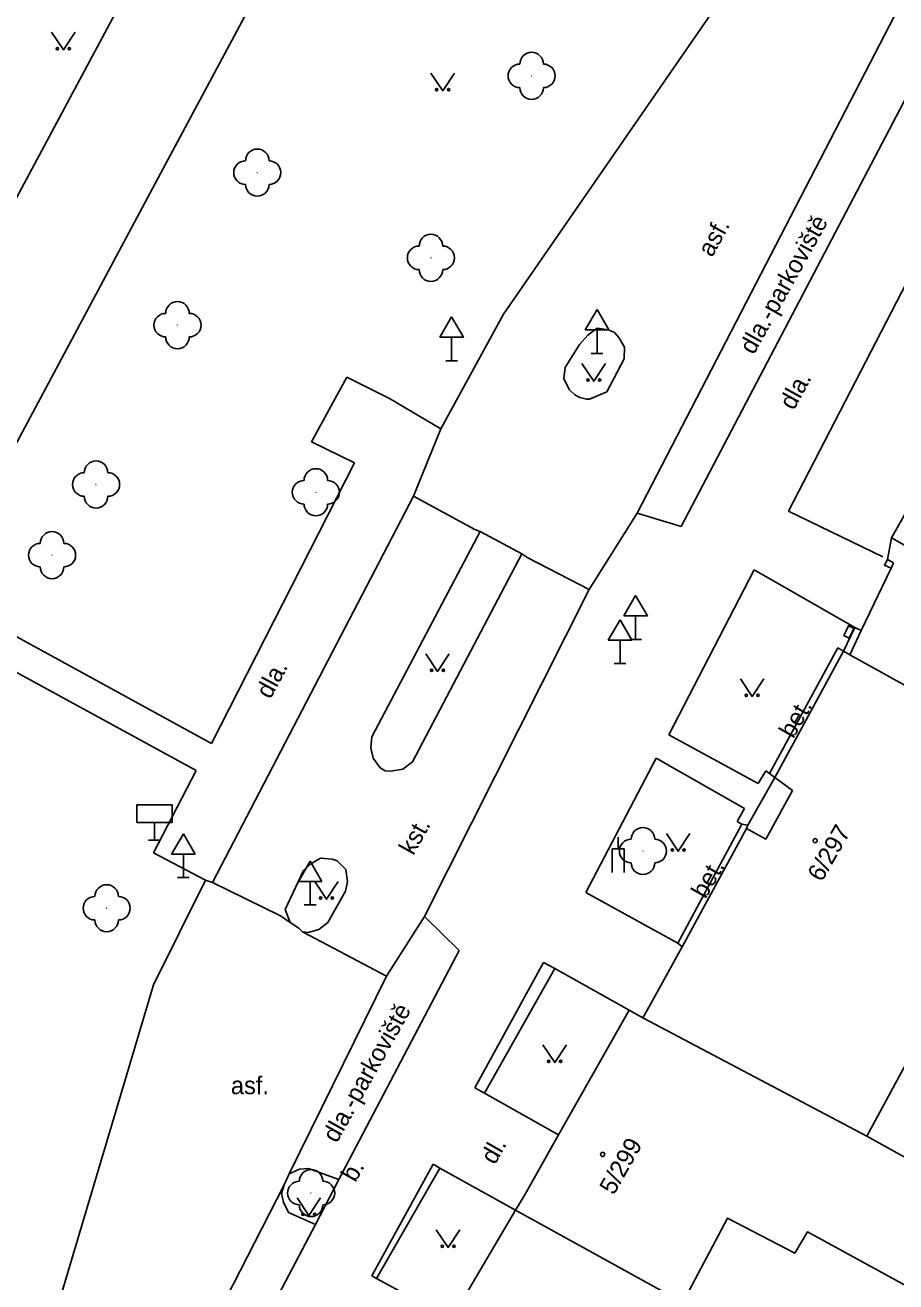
# Model space of a CAD drawing. Extents: x -577457 to -568404, y -1208466 to -1201387.
# Drawn here: x -568763.6 to -568726.6, y -1203865.9 to -1203812.5 of the extents above; entities that cross this region are included whole.
import ezdxf

# ---------------------------------------------------------------- set-up
doc = ezdxf.new("R2010")
doc.units = 0
for name, color, linetype in [('BUDOVY_MĚŘ', 7, 'Continuous'), ('BUDOVY_NEMĚŘ', 7, 'Continuous'), ('OBVOD_PILÍŘE', 7, 'Continuous'), ('POMOC_POPIS', 7, 'Continuous'), ('ROZHRANÍ_PLOCH', 7, 'Continuous'), ('ZELEŇ', 7, 'Continuous'), ('ZN_BUDOV', 7, 'Continuous'), ('ZN_DOPLŇKOVÉ', 7, 'Continuous'), ('ZN_KULTUR', 7, 'Continuous'), ('Č_POPIS_ORIENT', 7, 'Continuous')]:
    doc.layers.add(name, color=color, linetype=linetype)

msp = doc.modelspace()

# ---------------------------------------------------------------- linework, layer by layer
at = {"layer": 'BUDOVY_MĚŘ'}
for points in [[(-568722.45, -1203836.7), (-568726.8, -1203834.24), (-568719.81, -1203821.89)], [(-568731.77, -1203844.43), (-568728.84, -1203839.06)], [(-568728.84, -1203839.06), (-568728.58, -1203839.22)], [(-568732.97, -1203846.6), (-568732.15, -1203847.04), (-568731.02, -1203844.98), (-568731.77, -1203844.43)], [(-568735.7, -1203851.62), (-568732.97, -1203846.6)], [(-568732.97, -1203846.6), (-568732.91, -1203846.45)], [(-568737.37, -1203854.64), (-568737.06, -1203854.08)], [(-568740.96, -1203859.61), (-568737.95, -1203854.31)], [(-568737.95, -1203854.31), (-568737.37, -1203854.64)], [(-568742.78, -1203862.81), (-568742.39, -1203862.15)], [(-568745.5, -1203867.43), (-568742.78, -1203862.81)]]:
    msp.add_lwpolyline(points, dxfattribs=at)
at = {"layer": 'BUDOVY_NEMĚŘ'}
for points in [[(-568727.85, -1203859.67), (-568723.24, -1203851.14), (-568719.83, -1203853), (-568719, -1203851.58), (-568712.31, -1203855.22), (-568710.66, -1203852.43), (-568706.19, -1203855.51), (-568706.63, -1203856.32), (-568696.09, -1203863.7), (-568693.99, -1203860.65), (-568697.29, -1203858.38), (-568700.33, -1203856.28), (-568710.13, -1203849.53), (-568719.47, -1203844.25), (-568728.58, -1203839.22)], [(-568735.67, -1203866.73), (-568733.78, -1203863.15), (-568730.92, -1203864.64), (-568730.38, -1203863.73), (-568715.36, -1203871.94), (-568714.64, -1203870.66), (-568707.9, -1203874.89), (-568706.02, -1203872.29), (-568713.03, -1203867.89), (-568727.85, -1203859.67), (-568737.37, -1203854.64)], [(-568742.78, -1203862.81), (-568735.67, -1203866.73), (-568716.08, -1203877.89), (-568704.52, -1203884.7), (-568705.49, -1203886.4), (-568716.94, -1203879.81), (-568718.58, -1203882.69), (-568739.1, -1203871.07), (-568741.34, -1203874.97), (-568747.62, -1203871.05)]]:
    msp.add_lwpolyline(points, dxfattribs=at)
at = {"layer": 'OBVOD_PILÍŘE'}
msp.add_lwpolyline([(-568728.73, -1203838.19), (-568728.63, -1203837.98), (-568728.4, -1203838.09), (-568728.61, -1203838.51), (-568728.83, -1203838.4), (-568728.73, -1203838.19)], dxfattribs=at)
at = {"layer": 'ROZHRANÍ_PLOCH'}
for points in [[(-568750, -1203793.65), (-568756.6, -1203805.98), (-568767.65, -1203826.6)], [(-568743.29, -1203824.74), (-568730.72, -1203806.54)], [(-568752.1, -1203808.01), (-568757.98, -1203818.98)], [(-568737.62, -1203833.2), (-568726.47, -1203811.66)], [(-568725.08, -1203813.43), (-568735.74, -1203833.76)], [(-568723.73, -1203818.7), (-568731.18, -1203833.11)], [(-568757.98, -1203818.98), (-568767.4, -1203836.58)], [(-568745.96, -1203829.62), (-568743.29, -1203824.74)], [(-568739.71, -1203825.63), (-568740.06, -1203826.03)], [(-568739.31, -1203825.34), (-568739.71, -1203825.63)], [(-568738.83, -1203825.41), (-568739.31, -1203825.34)], [(-568738.58, -1203825.52), (-568738.83, -1203825.41)], [(-568738.4, -1203825.73), (-568738.58, -1203825.52)], [(-568738.15, -1203826.15), (-568738.4, -1203825.73)], [(-568740.06, -1203826.03), (-568740.67, -1203827.01)], [(-568738.16, -1203826.64), (-568738.15, -1203826.15)], [(-568738.9, -1203828.05), (-568738.16, -1203826.64)], [(-568751.45, -1203830.16), (-568749.96, -1203827.42)], [(-568748.14, -1203828.32), (-568749.96, -1203827.42)], [(-568740.67, -1203827.01), (-568740.73, -1203827.47)], [(-568740.73, -1203827.47), (-568740.5, -1203827.95)], [(-568740.5, -1203827.95), (-568740.26, -1203828.17)], [(-568748.14, -1203828.32), (-568745.96, -1203829.62)], [(-568740.26, -1203828.17), (-568740.05, -1203828.28)], [(-568740.05, -1203828.28), (-568739.77, -1203828.35)], [(-568739.77, -1203828.35), (-568739.64, -1203828.35)], [(-568739.64, -1203828.35), (-568738.9, -1203828.05)], [(-568745.96, -1203829.62), (-568747.12, -1203832.48)], [(-568751.45, -1203830.16), (-568749.63, -1203831.06)], [(-568749.63, -1203831.06), (-568755.71, -1203842.98)], [(-568755.66, -1203848.89), (-568747.12, -1203832.48)], [(-568747.12, -1203832.48), (-568744.51, -1203833.89)], [(-568739.66, -1203836.44), (-568737.62, -1203833.2)], [(-568737.62, -1203833.2), (-568735.74, -1203833.76)], [(-568731.18, -1203833.11), (-568727.18, -1203835.05)], [(-568744.29, -1203833.98), (-568748.89, -1203842.7)], [(-568744.51, -1203833.89), (-568744.29, -1203833.98)], [(-568744.29, -1203833.98), (-568742.52, -1203834.93)], [(-568742.52, -1203834.93), (-568747.16, -1203843.76)], [(-568742.26, -1203835.09), (-568742.52, -1203834.93)], [(-568739.66, -1203836.44), (-568742.26, -1203835.09)], [(-568732.64, -1203835.61), (-568736.27, -1203842.61)], [(-568732.64, -1203835.61), (-568728.36, -1203838.05)], [(-568739.66, -1203836.44), (-568746.65, -1203850.33)], [(-568755.71, -1203842.98), (-568767.4, -1203836.58)], [(-568768.05, -1203837.76), (-568756.35, -1203844.13)], [(-568731.99, -1203844.25), (-568729.09, -1203838.92)], [(-568728.84, -1203839.06), (-568729.09, -1203838.92)], [(-568748.89, -1203842.7), (-568748.94, -1203843.16)], [(-568732.47, -1203844.68), (-568736.27, -1203842.61)], [(-568748.94, -1203843.16), (-568748.83, -1203843.6)], [(-568748.83, -1203843.6), (-568748.53, -1203844.01)], [(-568747.58, -1203844.07), (-568747.16, -1203843.76)], [(-568736.81, -1203843.61), (-568739.8, -1203849.31)], [(-568736.81, -1203843.61), (-568733.05, -1203845.75)], [(-568758.17, -1203847.62), (-568756.35, -1203844.13)], [(-568748.53, -1203844.01), (-568748.32, -1203844.14)], [(-568748.32, -1203844.14), (-568748.1, -1203844.16)], [(-568748.1, -1203844.16), (-568747.58, -1203844.07)], [(-568732.47, -1203844.68), (-568732.15, -1203844.15)], [(-568732.15, -1203844.15), (-568731.99, -1203844.25)], [(-568731.99, -1203844.25), (-568731.77, -1203844.43)], [(-568733.05, -1203845.75), (-568733.36, -1203846.3)], [(-568735.89, -1203851.46), (-568733.16, -1203846.41)], [(-568733.36, -1203846.3), (-568733.16, -1203846.41)], [(-568733.16, -1203846.41), (-568732.91, -1203846.45)], [(-568755.96, -1203848.79), (-568758.17, -1203847.62)], [(-568751.48, -1203848.09), (-568751.79, -1203848.38)], [(-568751.07, -1203847.85), (-568751.48, -1203848.09)], [(-568751.07, -1203847.85), (-568750.58, -1203847.89)], [(-568750.58, -1203847.89), (-568750.36, -1203847.96)], [(-568750.36, -1203847.96), (-568750, -1203848.33)], [(-568755.96, -1203848.79), (-568758.17, -1203853.24)], [(-568755.96, -1203848.79), (-568755.66, -1203848.89)], [(-568751.79, -1203848.38), (-568752.57, -1203850.04)], [(-568750, -1203848.33), (-568749.92, -1203848.84)], [(-568755.66, -1203848.89), (-568752.77, -1203850.31)], [(-568750.01, -1203849.26), (-568750.76, -1203850.59)], [(-568749.92, -1203848.84), (-568750.01, -1203849.26)], [(-568735.89, -1203851.46), (-568739.8, -1203849.31)], [(-568752.36, -1203850.58), (-568752.77, -1203850.31)], [(-568752.57, -1203850.04), (-568752.36, -1203850.58)], [(-568746.65, -1203850.33), (-568748.27, -1203852.86)], [(-568745.18, -1203851.77), (-568746.65, -1203850.33)], [(-568752.36, -1203850.58), (-568752, -1203850.83)], [(-568752, -1203850.83), (-568751.84, -1203850.98)], [(-568751.6, -1203851.01), (-568751.14, -1203850.89)], [(-568751.14, -1203850.89), (-568750.76, -1203850.59)], [(-568751.27, -1203851.28), (-568751.84, -1203850.98)], [(-568751.84, -1203850.98), (-568751.6, -1203851.01)], [(-568748.27, -1203852.86), (-568751.27, -1203851.28)], [(-568735.89, -1203851.46), (-568735.7, -1203851.62)], [(-568750.3, -1203861.5), (-568745.18, -1203851.77)], [(-568741.6, -1203852.28), (-568744.51, -1203857.61)], [(-568741.6, -1203852.28), (-568741.12, -1203852.54)], [(-568752.4, -1203861.26), (-568748.27, -1203852.86)], [(-568758.17, -1203853.24), (-568762.38, -1203867.35)], [(-568744.51, -1203857.61), (-568744.1, -1203857.83)], [(-568752.4, -1203861.26), (-568751.97, -1203861.06)], [(-568751.97, -1203861.06), (-568751.58, -1203861.04)], [(-568751.58, -1203861.04), (-568750.3, -1203861.5)], [(-568748.69, -1203865.71), (-568748.89, -1203865.6), (-568746.29, -1203860.86)], [(-568746.29, -1203860.86), (-568746, -1203861.02)], [(-568752.4, -1203861.26), (-568752.61, -1203861.73)], [(-568751.28, -1203863.42), (-568750.3, -1203861.5)], [(-568760.69, -1203877.51), (-568752.61, -1203861.73)], [(-568752.61, -1203861.73), (-568752.73, -1203862.1)], [(-568752.73, -1203862.1), (-568752.65, -1203862.47)], [(-568752.65, -1203862.47), (-568752.43, -1203862.9)], [(-568752.43, -1203862.9), (-568751.28, -1203863.42)], [(-568751.28, -1203863.42), (-568758.93, -1203877.94)]]:
    msp.add_lwpolyline(points, dxfattribs=at)
at = {"layer": 'ZELEŇ'}
for centre in [(-568742.1, -1203814.62), (-568753.76, -1203818.73), (-568746.38, -1203822.35), (-568757.15, -1203825.21), (-568760.61, -1203831.98), (-568751.27, -1203832.31), (-568762.48, -1203834.98), (-568737.37, -1203847.55), (-568760.16, -1203849.98), (-568751.47, -1203862.08)]:
    msp.add_circle(centre, 0.0005, dxfattribs=at)
for centre, start, end in [((-568742.1, -1203814.12), 0, 180), ((-568742.6, -1203814.62), 90, 270), ((-568741.6, -1203814.62), 270, 90), ((-568742.1, -1203815.12), 180, 360), ((-568753.76, -1203818.23), 0, 180), ((-568754.26, -1203818.73), 90, 270), ((-568753.26, -1203818.73), 270, 90), ((-568753.76, -1203819.23), 180, 360), ((-568746.38, -1203821.85), 0, 180), ((-568746.88, -1203822.35), 90, 270), ((-568745.88, -1203822.35), 270, 90), ((-568746.38, -1203822.85), 180, 360), ((-568757.15, -1203824.71), 0, 180), ((-568757.65, -1203825.21), 90, 270), ((-568756.65, -1203825.21), 270, 90), ((-568757.15, -1203825.71), 180, 360), ((-568760.61, -1203831.48), 0, 180), ((-568761.11, -1203831.98), 90, 270), ((-568760.11, -1203831.98), 270, 90), ((-568751.27, -1203831.81), 0, 180), ((-568751.77, -1203832.31), 90, 270), ((-568750.77, -1203832.31), 270, 90), ((-568760.61, -1203832.48), 180, 360), ((-568751.27, -1203832.81), 180, 360), ((-568762.48, -1203834.48), 0, 180), ((-568762.98, -1203834.98), 90, 270), ((-568761.98, -1203834.98), 270, 90), ((-568762.48, -1203835.48), 180, 360), ((-568737.37, -1203847.05), 0, 180), ((-568737.87, -1203847.55), 90, 270), ((-568736.87, -1203847.55), 270, 90), ((-568737.37, -1203848.05), 180, 360), ((-568760.16, -1203849.48), 0, 180), ((-568760.66, -1203849.98), 90, 270), ((-568759.66, -1203849.98), 270, 90), ((-568760.16, -1203850.48), 180, 360), ((-568751.47, -1203861.58), 0, 180), ((-568751.97, -1203862.08), 90, 270), ((-568750.97, -1203862.08), 270, 90), ((-568751.47, -1203862.58), 180, 360)]:
    msp.add_arc(centre, 0.5, start, end, dxfattribs=at)
at = {"layer": 'ZN_BUDOV'}
for centre in [(-568730.05, -1203847.11), (-568739.08, -1203860.44)]:
    msp.add_circle(centre, 0.0875, dxfattribs=at)
at = {"layer": 'ZN_DOPLŇKOVÉ'}
for p, q in [((-568739.32, -1203824.544), (-568739.82, -1203825.41)), ((-568739.32, -1203824.544), (-568738.82, -1203825.41)), ((-568745.5, -1203824.854), (-568746, -1203825.72)), ((-568745.5, -1203824.854), (-568745, -1203825.72)), ((-568746, -1203825.72), (-568745, -1203825.72)), ((-568745.5, -1203826.72), (-568745.5, -1203825.72)), ((-568739.82, -1203825.41), (-568738.82, -1203825.41)), ((-568739.32, -1203826.41), (-568739.32, -1203825.41)), ((-568745.75, -1203826.72), (-568745.25, -1203826.72)), ((-568739.57, -1203826.41), (-568739.07, -1203826.41)), ((-568737.68, -1203836.694), (-568738.18, -1203837.56)), ((-568737.68, -1203836.694), (-568737.18, -1203837.56)), ((-568738.18, -1203837.56), (-568737.18, -1203837.56)), ((-568737.68, -1203838.56), (-568737.68, -1203837.56)), ((-568738.34, -1203837.724), (-568738.84, -1203838.59)), ((-568738.34, -1203837.724), (-568737.84, -1203838.59)), ((-568738.84, -1203838.59), (-568737.84, -1203838.59)), ((-568738.34, -1203839.59), (-568738.34, -1203838.59)), ((-568737.93, -1203838.56), (-568737.43, -1203838.56)), ((-568738.59, -1203839.59), (-568738.09, -1203839.59)), ((-568758.13, -1203846.34), (-568758.13, -1203847.09)), ((-568758.38, -1203847.09), (-568757.88, -1203847.09)), ((-568756.9, -1203846.814), (-568757.4, -1203847.68)), ((-568756.9, -1203846.814), (-568756.4, -1203847.68)), ((-568738.42, -1203847.46), (-568738.42, -1203846.96)), ((-568757.4, -1203847.68), (-568756.4, -1203847.68)), ((-568756.9, -1203848.68), (-568756.9, -1203847.68)), ((-568751.51, -1203847.974), (-568752.01, -1203848.84)), ((-568751.51, -1203847.974), (-568751.01, -1203848.84)), ((-568757.15, -1203848.68), (-568756.65, -1203848.68)), ((-568752.01, -1203848.84), (-568751.01, -1203848.84)), ((-568751.51, -1203849.84), (-568751.51, -1203848.84)), ((-568751.76, -1203849.84), (-568751.26, -1203849.84))]:
    msp.add_line(p, q, dxfattribs=at)
for points in [[(-568726.8, -1203834.24), (-568726.98, -1203835.16)], [(-568726.82, -1203835.53), (-568727.1, -1203835.41), (-568726.98, -1203835.16)], [(-568726.98, -1203835.16), (-568726.72, -1203835.31)], [(-568726.72, -1203835.31), (-568726.82, -1203835.53)], [(-568726.82, -1203835.53), (-568728.09, -1203838.18)], [(-568728.09, -1203838.18), (-568728.36, -1203838.05), (-568728.84, -1203839.06)], [(-568728.09, -1203838.18), (-568728.58, -1203839.22)], [(-568732.91, -1203846.45), (-568731.77, -1203844.43)], [(-568738.67, -1203848.46), (-568738.67, -1203847.46), (-568738.17, -1203847.46), (-568738.17, -1203848.46)], [(-568735.7, -1203851.62), (-568737.06, -1203854.08)], [(-568744.1, -1203857.83), (-568741.12, -1203852.54)], [(-568741.12, -1203852.54), (-568737.95, -1203854.31)], [(-568740.96, -1203859.61), (-568744.1, -1203857.83)], [(-568742.39, -1203862.15), (-568740.96, -1203859.61)], [(-568748.69, -1203865.71), (-568746, -1203861.02)], [(-568746, -1203861.02), (-568742.78, -1203862.81)], [(-568748.69, -1203865.71), (-568745.77, -1203867.29)]]:
    msp.add_lwpolyline(points, dxfattribs=at)
msp.add_lwpolyline([(-568758.88, -1203846.34), (-568757.38, -1203846.34), (-568757.38, -1203845.59), (-568758.88, -1203845.59)], close=True, dxfattribs=at)
at = {"layer": 'ZN_KULTUR'}
for points in [[(-568762.5, -1203812.77), (-568762, -1203813.52), (-568761.5, -1203812.77)], [(-568746.38, -1203814.5), (-568745.88, -1203815.25), (-568745.38, -1203814.5)], [(-568739.96, -1203826.84), (-568739.46, -1203827.59), (-568738.96, -1203826.84)], [(-568746.6, -1203839.17), (-568746.1, -1203839.92), (-568745.6, -1203839.17)], [(-568733.23, -1203840.24), (-568732.73, -1203840.99), (-568732.23, -1203840.24)], [(-568736.37, -1203846.81), (-568735.87, -1203847.56), (-568735.37, -1203846.81)], [(-568751.32, -1203848.85), (-568750.82, -1203849.6), (-568750.32, -1203848.85)], [(-568741.62, -1203855.79), (-568741.12, -1203856.54), (-568740.62, -1203855.79)], [(-568752.07, -1203862.28), (-568751.57, -1203863.03), (-568751.07, -1203862.28)], [(-568746.15, -1203863.64), (-568745.65, -1203864.39), (-568745.15, -1203863.64)]]:
    msp.add_lwpolyline(points, dxfattribs=at)
for centre in [(-568762.25, -1203813.47), (-568761.75, -1203813.47), (-568746.13, -1203815.2), (-568745.63, -1203815.2), (-568739.71, -1203827.54), (-568739.21, -1203827.54), (-568746.35, -1203839.87), (-568745.85, -1203839.87), (-568732.98, -1203840.94), (-568732.48, -1203840.94), (-568736.12, -1203847.51), (-568735.62, -1203847.51), (-568751.07, -1203849.55), (-568750.57, -1203849.55), (-568741.37, -1203856.49), (-568740.87, -1203856.49), (-568751.82, -1203862.98), (-568751.32, -1203862.98), (-568745.9, -1203864.34), (-568745.4, -1203864.34)]:
    msp.add_circle(centre, 0.05, dxfattribs=at)

# ---------------------------------------------------------------- texts
at = {"layer": 'POMOC_POPIS'}
for s, rotation, p in [('asf.', 61.17, (-568734.43, -1203822.36)), ('dla.-parkoviště', 60.82, (-568732.66, -1203826.5)), ('dla.', 61.31, (-568730.96, -1203828.86)), ('dla.', 61.7, (-568753.2, -1203841.13)), ('bet.', 60.04, (-568730.98, -1203842.81)), ('kst.', 60.77, (-568747.13, -1203847.77)), ('bet.', 60.04, (-568734.71, -1203849.62)), ('dla.-parkoviště', 60.82, (-568750.38, -1203859.99)), ('dl.', 60.39, (-568743.66, -1203860.91)), ('b.', 60.39, (-568749.59, -1203861.66))]:
    msp.add_text(s, height=0.75, rotation=rotation, dxfattribs=at).set_placement(p)
msp.add_text('asf.', height=0.75, dxfattribs=at).set_placement((-568754.88, -1203857.88))
at = {"layer": 'Č_POPIS_ORIENT'}
for s, rotation, p in [('6/297', 60, (-568729.77, -1203848.9)), ('5/299', 60.39, (-568738.61, -1203862.2))]:
    msp.add_text(s, height=0.75, rotation=rotation, dxfattribs=at).set_placement(p)

doc.saveas('drawing.dxf')
